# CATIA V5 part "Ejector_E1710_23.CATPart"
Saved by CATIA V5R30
Part number: Vyhazovac_7x160
Nomenclature: E1710/7x160
Description: MEUSBURGER
Property "Material": "1.221"
Publications: "__DrillHole", "Base"
Bounding box of the stored display mesh (mm): x -5.992 to 5.992, y -5.992 to 5.992, z 0 to 151
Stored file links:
  E:\Bakalarka\Model\Forma_v7\Ejector_E1710_23.CATPart
  E:\dev\MoldDesign\intel_a\startup\components\MoldCatalog\Ejector\Meusburger\Ejector_E1710\TableE1710.txt
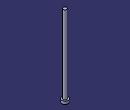
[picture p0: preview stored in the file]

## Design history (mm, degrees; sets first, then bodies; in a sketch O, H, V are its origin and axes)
Parameters
  Ref = "E1710/7x160" {design table}
  D1 = 7 mm {design table}
  D3 = 12 mm {design table}
  L = 160 mm {design table}
  L3 = 5 mm {design table}
  R = 0.5 mm {design table}
  k_d3 = 13 mm {design table}
  k_d1 = 7.2 mm {design table}
  k_F = 0.5 mm {design table}
  kl = 17 mm {design table}
  Mat = "1.221" {design table}
  HeatTreat = "ISO6751" {design table}
  Offset_Parting = 10 mm
  Anti_Rotation = "Normal"
  Anti_Rotation_D = 4 mm
  Anti_Rotation_D_Icut = 4 mm
  Add_Length_L = 1.3377 mm
  Add_Length_D3 = 0 mm
  SupplierRef = "Meusburger 2017"
  BmpRef = "F_MldEjectorD1"
  DrillHole_Length = 225 mm
  ValidationTest = false
  Anti_Rotation_D_min = 4 mm {= OffSet_D1 /2}
  Anti_Rotation_D_max = 5.925 mm {= D3/2-0.075mm}
  Anti_Rotation_D_ref = 4 mm {= Anti_Rotation_D}
  Anti_Rotation_D_Icut_ref = 4 mm {= Anti_Rotation_D_Icut}
  Anti_Rotation_Ref_Icut = 2.3246 mm
  Offset_L = 20 mm
  D = 7 mm {= D1}
  OffSet_D1 = 8 mm {= D1+2*R}
  OffSet_D3 = 13 mm {= D3+1mm}
  XG_Split = -125.5 mm
  YG_Split = -4 mm
  ZG_Split = -198 mm
  DirX_Split = 0 mm
  DirY_Split = 0 mm
  DirZ_Split = 1 mm
Set1 "BaseBody"
  Point1 "Base": (0, 0, 0)
  Plane1: type Offset, RefPlane xy-plane, Offset 225 {= DrillHole_Length}, reversed
  Sketch1 "Sketch.2" on xy-plane, origin (0, 0, 0), H (1, 0, 0), V (0, 1, 0)
    point P1 (-0.46, 1.1623)
    point P2 (0.46, 1.1623)
    construction line L1 (-0.46, 1.1623) -> (0.46, 1.1623)
    point P3 (0.46, -1.1623)
    line L2 (0.46, -1.1623) -> (0.46, 1.1623)
    point P4 (-0.46, -1.1623)
    construction line L3 (0.46, -1.1623) -> (-0.46, -1.1623)
    line L4 (-0.46, 1.1623) -> (-0.46, -1.1623)
    point P5 (-0.21, 1.1623)
    arc A1 centre (-0.21, 1.1623) radius 0.25 from (-0.21, 1.4123) to (-0.46, 1.1623) ccw
    point P7 (0.21, 1.1623)
    point P8 (0.21, 1.4123)
    arc A2 centre (0.21, 1.1623) radius 0.25 from (0.46, 1.1623) to (0.21, 1.4123) ccw
    line L5 (-0.21, 1.4123) -> (0.21, 1.4123)
    point P9 (-0.46, -1.1623)
    arc A3 centre (-0.21, -1.1623) radius 0.25 from (-0.46, -1.1623) to (-0.21, -1.4123) ccw
    point P11 (0.21, -1.4123)
    line L6 (-0.21, -1.4123) -> (0.21, -1.4123)
    point P12 (0.46, -1.1623)
    arc A4 centre (0.21, -1.1623) radius 0.25 from (0.21, -1.4123) to (0.46, -1.1623) ccw
    point P14 (-0.46, 1.1623)
    point P15 (-0.46, -1.1623)
    point P16 (0.46, 1.1623)
    point P17 (0.46, -1.1623)
    reference projected circle E1 centre (0, 0) radius 1.25 from edge [face of Shaft1 from Sketch2.L3 | face of Shaft1 from Sketch2.L4]
    reference projected circle E2 centre (0, 0) radius 1.25 from edge [face of Shaft1 from Sketch2.L3 | face of Shaft1 from Sketch2.L4]
    reference projected circle E3 centre (0, 0) radius 1.25 from edge [face of Shaft1 from Sketch2.L3 | face of Shaft1 from Sketch2.L4]
    reference projected circle E4 centre (0, 0) radius 1.25 from edge [face of Shaft1 from Sketch2.L3 | face of Shaft1 from Sketch2.L4]
    point P18 (-0.46, -1.1623)
    point P19 (-0.21, -1.4123)
    point P20 (0.21, -1.4123)
    point P21 (0.46, -1.1623)
    point P22 (-0.21, -1.4123)
    point P23 (0.21, -1.4123)
    distance P14 P15 = 2.3246 (reference)
    distance P16 P17 = 2.3246 (reference)
    distance L1 P14 = 0 (reference)
    radius A1 = 3.5
    distance L4 V = 4.01
    distance L2 V = 5.935
    distance L5 L6 = 12
    horizontal: L1 H, L3 H, L5 H
    vertical: L2 V, L4 V
    coincidence: P5 L1, P7 L1, P3 P12, P14 L4, P15 L4, P16 L2, P17 L2, P14 E1, P15 E2, P16 E3, P17 E4, P3 P21, P4 P18, P20 P23, P19 P22
    tangency: A1 L4, A2 L2, A2 L5, A1 L5
    symmetry: P1 P9 H, A1 A3 H, P8 P11 H, L5 L6 H, P2 P12 H, A2 A4 H
  DatumSurface1
Body1 "PartBody" (main body)
  Sketch2 "Sketch.1" on zx-plane, origin (0, 0, 0), H (-1, 0, 0), V (0, 0, 1)
    point P1 (0, 160)
    line L1 (3.5, 160) -> (0, 160)
    line L2 (3.5, 5) -> (3.5, 160)
    line L3 (6, 5) -> (3.5, 5)
    line L4 (6, 0) -> (6, 5)
    point P5 (0, 0)
    line L5 (0, 0) -> (6, 0)
    point P6 (0, 160)
    axis line L6 (0, 160) -> (0, 0)
    point P7 (0, 0)
    point P8 (3.5, 5)
    point P9 (3.5, 5)
    line L7 (0, 160) -> (0, 0)
    distance L5 L3 = 5 {= L3}
    distance L5 L1 = 160 {= L}
    distance L2 L6 = 3.5 {= D1 /2}
    distance L4 L6 = 6 {= D3 /2}
    coincidence: L6 P5, P1 L6, L5 H, L6 V, P7 O, P6 P1, P8 P9
    vertical: L2 V, L7 V
    horizontal: L1 H
  Shaft1 "Shaft.1": profile Sketch2, axis Sketch2.L6, angle 360
  Pocket1: profile face of Shaft1 from Sketch2.L1, direction along face of Shaft1 from Sketch2.L1 reversed, up to face of DatumSurface1
  Pocket2 "Pocket.1": profile Sketch1, direction (0, 0, 1), length 6, outer side, deactivated
  Pocket3 "Pocket.2": profile Sketch1, direction (0, 0, 1), length 6, outer side, deactivated
  Fillet1: radius 0.5 {= R}, on edge [face of Shaft1 from Sketch2.L2 | face of Shaft1 from Sketch2.L3]
Body2 "__DrillHole"
  Sketch3 "Sketch.3" on face of Shaft1, origin (0, 0, 0), H (1, 0, 0), V (0, -1, 0)
    point P1 (0, 0)
    reference projected point E1 (0, 0) from Point1
    coincidence: E1 P1
  Hole1 "Hole.1": placed by Sketch3, at (0, 0, 0) direction (0, 0, 1), diameter 8 {= OffSet_D1}, depth 140 {= L-Offset_L}
  Sketch4 "Sketch.4" on face of Shaft1, origin (0, 0, 0), H (1, 0, 0), V (0, -1, 0)
    point P1 (0, 0)
    reference projected point E1 (0, 0) from Point1
    coincidence: E1 P1
  Hole2 "Hole.2": placed by Sketch4, at (0, 0, 0) direction (0, 0, 1), diameter 7 {= D1}, depth 160 {= L}
  Sketch5 "Sketch.5" on face of Shaft1 from Sketch2.L3, origin (0, 0, 5), H (1, 0, 0), V (0, 1, 0)
    point P1 (0, 0)
    reference projected point E1 (0, 0) from Point1
    coincidence: E1 P1
  Hole3 "Hole.3": placed by Sketch5, at (0, 0, 5) direction (0, 0, -1), diameter 13 {= OffSet_D3}, depth 230 {= L3 +DrillHole_Length}
  Chamfer1: length 0.5 {= k_F}, angle 45, on edge [face of Hole1 | face of Hole3]
  Body3 "__Body.1"
    Pocket4 "Pocket.3": profile Sketch1, direction (0, 0, -1), length 225, opposite side length 5, deactivated
  Assemble1: tool Body3
  Chamfer2: length 0.5 {= k_F}, angle 45, on edge [start face of Pocket4 | face of Hole1], deactivated
  Body4 "__Body.2"
    Pocket5 "Pocket.4": profile Sketch1, direction (0, 0, -1), length 225, opposite side length 5, deactivated
  Assemble2: tool Body4
  Chamfer3: length 0.5 {= k_F}, angle 45, on edge [start face of Pocket5 | face of Hole1], deactivated
Current feature: Pocket1
Relations
  design table "TableE1710", configuration 278, drives Ref, D1, D3, L, L3, R, k_d3, k_d1, k_F, kl, Mat, HeatTreat
  Offset_L = 20mm (deactivated)
  rule "Cut_Head_rule":
    let sketch_cut (length)
    let PartBody_Pocket_Sketch (Boolean)
    let I_PartBody_Pocket (Boolean)
    let D_PartBody_Pocket (Boolean)
    let N_DrillHole_Hole (Boolean)
    let N_DrillHole_Hole_Sketch (Boolean)
    let I_DrillHole_Pocket (Boolean)
    let D_DrillHole_Pocket (Boolean)
    /* --------------------------------------------------------------------------------------*/
    if Anti_Rotation =="Normal"
    {
    	sketch_cut=Anti_Rotation_D_max
    	PartBody_Pocket_Sketch = false
    	I_PartBody_Pocket = false
    	D_PartBody_Pocket = false
    	N_DrillHole_Hole = true
    	N_DrillHole_Hole_Sketch = true
    	I_DrillHole_Pocket = false
    	D_DrillHole_Pocket = false
    	Chamfer1.Activity= true
    	Chamfer2.Activity= false
    	Chamfer3.Activity= false
    }
    if Anti_Rotation == "I_Cut"
    {
    	sketch_cut=Anti_Rotation_D_Icut_ref
    	PartBody_Pocket_Sketch = true
    	I_PartBody_Pocket = true
    	D_PartBody_Pocket = false
    	N_DrillHole_Hole = false
    	N_DrillHole_Hole_Sketch = false
    	I_DrillHole_Pocket = true
    	D_DrillHole_Pocket = false
    	Chamfer1.Activity= false
    	Chamfer2.Activity= true
    	Chamfer3.Activity= false
    }
    if Anti_Rotation =="D_Cut"
    {
    	sketch_cut=Anti_Rotation_D_max
    	PartBody_Pocket_Sketch = true
    	I_PartBody_Pocket = false
    	D_PartBody_Pocket = true
    	N_DrillHole_Hole = false
    	N_DrillHole_Hole_Sketch = false
    	I_DrillHole_Pocket = false
    	D_DrillHole_Pocket = true
    	Chamfer1.Activity= false
    	Chamfer2.Activity= false
    	Chamfer3.Activity= true
    }
    /* --------------------------------------------------------------------------------------*/
    Sketch1.distance(L2 V) = sketch_cut+0.01mm
    Sketch1.distance(L4 V) =Anti_Rotation_D_ref+0.01mm
    Sketch1.radius(A1) =D/2
    Pocket4.FirstLimit.Depth = DrillHole_Length
    Pocket5.FirstLimit.Depth = DrillHole_Length
    Pocket2.FirstLimit.Depth = L3+1mm
    Pocket3.FirstLimit.Depth = L3+1mm
    Pocket4.SecondLimit.Depth = L3
    Pocket5.SecondLimit.Depth =L3
    Pocket2.Activity = I_PartBody_Pocket
    Pocket3.Activity = D_PartBody_Pocket
    Sketch1.Activity =PartBody_Pocket_Sketch
    Hole3.Activity= N_DrillHole_Hole
    Sketch5.Activity = N_DrillHole_Hole_Sketch
    Pocket4.Activity = I_DrillHole_Pocket
    Pocket5.Activity  = D_DrillHole_Pocket
  rule "Anti_Rotation_Icut_constrain":
    let Ref1(length)
    let Ref2(length)
    let Ref3(length)
    let Diam1(length)
    let Diam2(length)
    let Add_Length_Lmin (length)
    Ref1=Sketch1.distance(P14 P15)
    Ref2=Sketch1.distance(P16 P17)
    Diam1=D
    Diam2=D3
    /* --------------------------------------------------------------------*/
    if Ref1 >Ref2
    	Anti_Rotation_Ref_Icut = Ref1
    else
    	Anti_Rotation_Ref_Icut  =Ref2
    Add_Length_D3 .InferiorRange=Anti_Rotation_Ref_Icut /2+Diam1/2 -Diam2/2
    if Add_Length_D3 .InferiorRange<0mm
    	Add_Length_D3 .InferiorRange=0mm
    if ValidationTest == "true"
    	Ref3   = 2*Add_Length_L +Anti_Rotation_Ref_Icut  +2*Diam1/2
    else
    	Ref3  =Diam2+2*Add_Length_D3
    if Ref3 <Diam2
    {
    	Ref3 =Diam2
    }
    /* --------------------------------------------------------------------*/
    Sketch1.distance(L5 L6) = Ref3
    Add_Length_L .InferiorRange=Diam2/2-Anti_Rotation_Ref_Icut/2-Diam1/2
    Add_Length_Lmin=Diam2/2-Anti_Rotation_Ref_Icut/2-Diam1/2
    if Add_Length_Lmin<0mm
    	Add_Length_L .InferiorRange=0mm
    else
    	Add_Length_L .InferiorRange=Add_Length_Lmin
